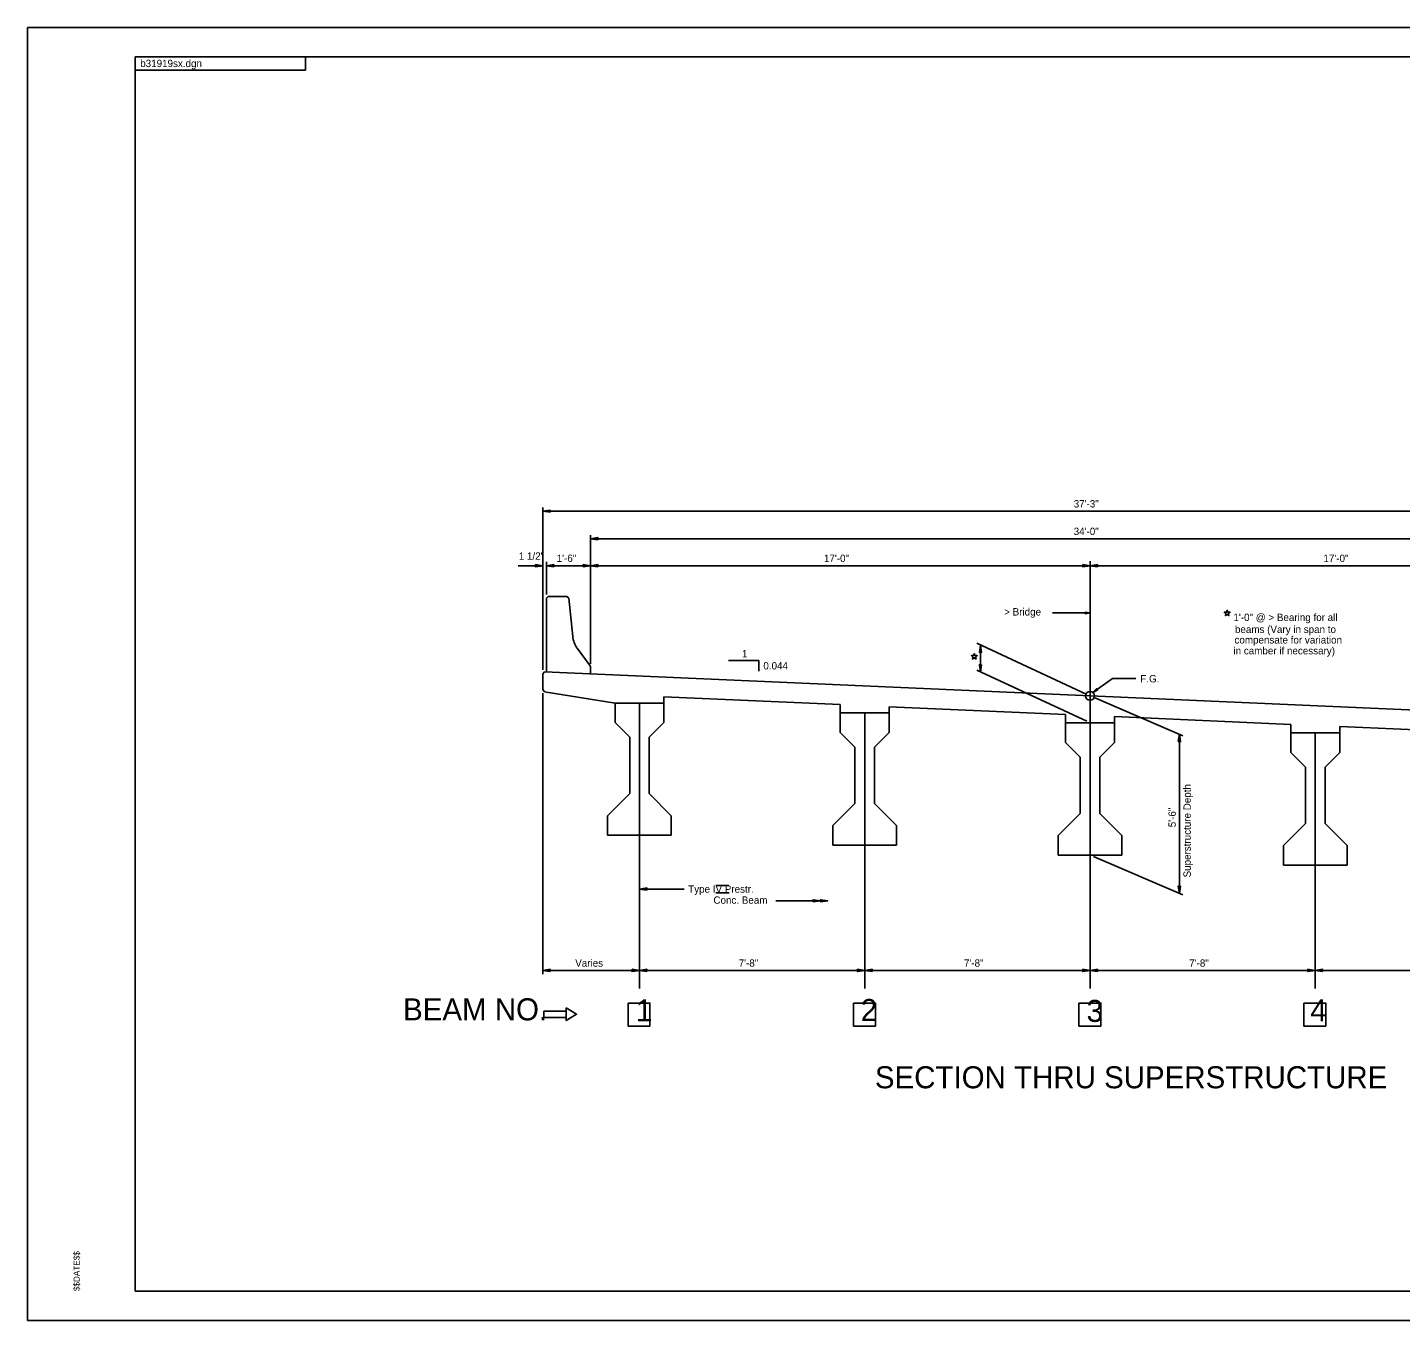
# Model space of a CAD drawing. Extents: x 9680018.4 to 9680090.7, y 4198568.1 to 4198612.1.
# Drawn here: x 9680018.44 to 9680065.17, y 4198568.13 to 4198612.13 of the extents above; entities that cross this region are included whole.
import ezdxf

# ---------------------------------------------------------------- set-up
doc = ezdxf.new("R2010")
doc.units = 0
for name, color, linetype in [('BR_AUTO DIMENSION', 7, 'Continuous'), ('BR_BORDER LINES', 7, 'Continuous'), ('BR_CENTER LINES', 7, 'Continuous'), ('BR_CONCRETE', 7, 'Continuous'), ('BR_REBAR', 7, 'Continuous'), ('BR_TEXT', 7, 'Continuous'), ('RD_SHT_IplotShp', 7, 'Continuous')]:
    doc.layers.add(name, color=color, linetype=linetype)

msp = doc.modelspace()

# ---------------------------------------------------------------- linework, layer by layer
at = {"layer": 'BR_AUTO DIMENSION'}
for p, q in [((9680035.978, 4198593.94), (9680035.978, 4198595.795)), ((9680035.978, 4198595.67), (9680073.228, 4198595.67)), ((9680037.603, 4198593.94), (9680037.603, 4198594.857)), ((9680037.603, 4198594.732), (9680071.603, 4198594.732)), ((9680035.144, 4198593.815), (9680035.978, 4198593.815)), ((9680035.978, 4198590.265), (9680035.978, 4198593.94)), ((9680036.103, 4198592.832), (9680036.103, 4198593.94)), ((9680036.103, 4198593.815), (9680054.603, 4198593.815)), ((9680037.603, 4198590.479), (9680037.603, 4198593.94)), ((9680037.999, 4198593.815), (9680037.603, 4198593.815)), ((9680054.603, 4198593.815), (9680073.103, 4198593.815)), ((9680053.327, 4198592.206), (9680054.603, 4198592.206)), ((9680054.434, 4198592.177), (9680054.434, 4198592.234)), ((9680054.434, 4198592.234), (9680054.603, 4198592.206)), ((9680054.603, 4198592.206), (9680054.434, 4198592.177)), ((9680054.468, 4198589.445), (9680050.747, 4198591.173)), ((9680050.875, 4198591.113), (9680050.875, 4198590.196)), ((9680054.49, 4198588.518), (9680050.747, 4198590.255)), ((9680035.978, 4198589.473), (9680035.978, 4198579.917)), ((9680054.74, 4198589.324), (9680057.76, 4198588.03)), ((9680057.646, 4198588.079), (9680057.646, 4198582.662)), ((9680039.603, 4198587.244), (9680039.603, 4198586.767)), ((9680047.27, 4198586.906), (9680047.27, 4198586.429)), ((9680054.936, 4198586.569), (9680054.936, 4198586.092)), ((9680062.603, 4198586.232), (9680062.603, 4198585.755)), ((9680054.718, 4198583.916), (9680057.76, 4198582.613)), ((9680040.794, 4198582.812), (9680039.27, 4198582.812)), ((9680041.867, 4198582.935), (9680042.313, 4198582.935)), ((9680041.87, 4198582.685), (9680042.316, 4198582.685)), ((9680045.677, 4198582.407), (9680043.912, 4198582.407)), ((9680035.978, 4198580.042), (9680039.27, 4198580.042)), ((9680039.27, 4198580.042), (9680046.936, 4198580.042)), ((9680039.27, 4198579.917), (9680039.27, 4198579.917)), ((9680046.936, 4198580.042), (9680054.603, 4198580.042)), ((9680046.936, 4198579.917), (9680046.936, 4198579.917)), ((9680054.603, 4198580.042), (9680062.27, 4198580.042)), ((9680054.603, 4198579.917), (9680054.603, 4198579.917)), ((9680062.27, 4198580.042), (9680069.936, 4198580.042)), ((9680062.27, 4198579.917), (9680062.27, 4198579.917))]:
    msp.add_line(p, q, dxfattribs=at)
for points in [[(9680036.228, 4198595.632), (9680035.978, 4198595.67), (9680036.228, 4198595.707)], [(9680037.853, 4198594.695), (9680037.603, 4198594.732), (9680037.853, 4198594.77)], [(9680035.728, 4198593.853), (9680035.978, 4198593.815), (9680035.728, 4198593.778)], [(9680036.353, 4198593.778), (9680036.103, 4198593.815), (9680036.353, 4198593.853)], [(9680037.353, 4198593.853), (9680037.603, 4198593.815), (9680037.353, 4198593.778)], [(9680037.853, 4198593.778), (9680037.603, 4198593.815), (9680037.853, 4198593.853)], [(9680037.853, 4198593.778), (9680037.603, 4198593.815), (9680037.853, 4198593.853)], [(9680054.353, 4198593.853), (9680054.603, 4198593.815), (9680054.353, 4198593.778)], [(9680054.853, 4198593.778), (9680054.603, 4198593.815), (9680054.853, 4198593.853)], [(9680050.838, 4198590.863), (9680050.875, 4198591.113), (9680050.913, 4198590.863)], [(9680050.913, 4198590.446), (9680050.875, 4198590.196), (9680050.838, 4198590.446)], [(9680054.864, 4198589.585), (9680054.694, 4198589.5), (9680054.832, 4198589.631)], [(9680057.608, 4198587.829), (9680057.646, 4198588.079), (9680057.683, 4198587.829)], [(9680039.52, 4198582.775), (9680039.27, 4198582.812), (9680039.52, 4198582.85)], [(9680057.683, 4198582.912), (9680057.646, 4198582.662), (9680057.608, 4198582.912)], [(9680045.177, 4198582.37), (9680045.427, 4198582.407), (9680045.177, 4198582.445)], [(9680045.427, 4198582.37), (9680045.677, 4198582.407), (9680045.427, 4198582.445)], [(9680036.228, 4198580.004), (9680035.978, 4198580.042), (9680036.228, 4198580.079)], [(9680039.02, 4198580.079), (9680039.27, 4198580.042), (9680039.02, 4198580.004)], [(9680039.52, 4198580.004), (9680039.27, 4198580.042), (9680039.52, 4198580.079)], [(9680046.686, 4198580.079), (9680046.936, 4198580.042), (9680046.686, 4198580.004)], [(9680047.186, 4198580.004), (9680046.936, 4198580.042), (9680047.186, 4198580.079)], [(9680054.353, 4198580.079), (9680054.603, 4198580.042), (9680054.353, 4198580.004)], [(9680054.853, 4198580.004), (9680054.603, 4198580.042), (9680054.853, 4198580.079)], [(9680062.02, 4198580.079), (9680062.27, 4198580.042), (9680062.02, 4198580.004)], [(9680062.52, 4198580.004), (9680062.27, 4198580.042), (9680062.52, 4198580.079)]]:
    msp.add_lwpolyline(points, close=True, dxfattribs=at)
msp.add_circle((9680054.603, 4198589.383), 0.149, dxfattribs=at)
at = {"layer": 'BR_BORDER LINES'}
for p, q in [((9680018.439, 4198612.13), (9680090.439, 4198612.13)), ((9680089.439, 4198611.127), (9680022.106, 4198611.127)), ((9680022.106, 4198569.127), (9680022.106, 4198611.127)), ((9680027.906, 4198611.127), (9680027.906, 4198610.676)), ((9680022.106, 4198610.676), (9680027.906, 4198610.676)), ((9680022.106, 4198569.127), (9680089.439, 4198569.127))]:
    msp.add_line(p, q, dxfattribs=at)
at = {"layer": 'BR_CENTER LINES'}
for p, q in [((9680054.603, 4198593.97), (9680054.603, 4198579.422)), ((9680038.436, 4198589.14), (9680040.103, 4198589.14)), ((9680039.27, 4198589.14), (9680039.27, 4198579.422)), ((9680046.103, 4198588.803), (9680047.77, 4198588.803)), ((9680046.936, 4198588.803), (9680046.936, 4198579.422)), ((9680053.77, 4198588.466), (9680055.436, 4198588.466)), ((9680061.436, 4198588.128), (9680063.103, 4198588.128)), ((9680062.27, 4198588.128), (9680062.27, 4198579.422))]:
    msp.add_line(p, q, dxfattribs=at)
at = {"layer": 'BR_CONCRETE'}
for p, q in [((9680036.166, 4198592.77), (9680036.103, 4198592.707)), ((9680036.103, 4198592.707), (9680036.103, 4198590.197)), ((9680036.166, 4198592.77), (9680036.791, 4198592.77)), ((9680036.791, 4198592.77), (9680036.86, 4198592.708)), ((9680036.996, 4198591.408), (9680036.86, 4198592.708)), ((9680037.587, 4198590.403), (9680037.15, 4198591.006)), ((9680035.978, 4198590.14), (9680036.04, 4198590.2)), ((9680035.978, 4198590.14), (9680035.978, 4198589.598)), ((9680036.04, 4198590.2), (9680073.166, 4198588.566)), ((9680037.603, 4198590.354), (9680037.603, 4198590.131)), ((9680036.04, 4198589.525), (9680035.978, 4198589.598)), ((9680036.04, 4198589.525), (9680038.436, 4198589.14)), ((9680040.103, 4198589.354), (9680046.103, 4198589.09)), ((9680047.77, 4198589.016), (9680053.77, 4198588.752)), ((9680055.436, 4198588.679), (9680061.436, 4198588.415)), ((9680063.103, 4198588.342), (9680069.103, 4198588.078))]:
    msp.add_line(p, q, dxfattribs=at)
for centre, radius, start, end in [((9680037.825, 4198591.495), 0.833, 186.009, 215.9195), ((9680037.52, 4198590.354), 0.0833, 360, 35.9195)]:
    msp.add_arc(centre, radius, start, end, dxfattribs=at)
at = {"layer": 'BR_REBAR'}
for p, q in [((9680042.303, 4198590.587), (9680043.332, 4198590.587)), ((9680043.332, 4198590.587), (9680043.332, 4198590.222)), ((9680038.436, 4198588.474), (9680038.436, 4198589.14)), ((9680038.436, 4198589.14), (9680040.103, 4198589.14)), ((9680040.103, 4198588.474), (9680040.103, 4198589.354)), ((9680046.103, 4198588.136), (9680046.103, 4198589.09)), ((9680046.103, 4198588.803), (9680047.77, 4198588.803)), ((9680047.77, 4198588.136), (9680047.77, 4198589.016)), ((9680053.77, 4198587.799), (9680053.77, 4198588.752)), ((9680055.436, 4198587.799), (9680055.436, 4198588.679)), ((9680038.436, 4198588.474), (9680038.936, 4198587.974)), ((9680040.103, 4198588.474), (9680039.603, 4198587.974)), ((9680046.103, 4198588.136), (9680046.603, 4198587.636)), ((9680047.77, 4198588.136), (9680047.27, 4198587.636)), ((9680053.77, 4198588.466), (9680055.436, 4198588.466)), ((9680061.436, 4198587.462), (9680061.436, 4198588.415)), ((9680061.436, 4198588.128), (9680063.103, 4198588.128)), ((9680063.103, 4198587.462), (9680063.103, 4198588.342)), ((9680038.936, 4198586.057), (9680038.936, 4198587.974)), ((9680039.603, 4198586.057), (9680039.603, 4198587.974)), ((9680053.77, 4198587.799), (9680054.27, 4198587.299)), ((9680055.436, 4198587.799), (9680054.936, 4198587.299)), ((9680046.603, 4198585.72), (9680046.603, 4198587.636)), ((9680047.27, 4198585.72), (9680047.27, 4198587.636)), ((9680054.27, 4198585.382), (9680054.27, 4198587.299)), ((9680054.936, 4198585.382), (9680054.936, 4198587.299)), ((9680061.436, 4198587.462), (9680061.936, 4198586.962)), ((9680063.103, 4198587.462), (9680062.603, 4198586.962)), ((9680061.936, 4198585.045), (9680061.936, 4198586.962)), ((9680062.603, 4198585.045), (9680062.603, 4198586.962)), ((9680038.936, 4198586.057), (9680038.186, 4198585.307)), ((9680039.603, 4198586.057), (9680040.353, 4198585.307)), ((9680046.603, 4198585.72), (9680045.853, 4198584.97)), ((9680047.27, 4198585.72), (9680048.02, 4198584.97)), ((9680054.27, 4198585.382), (9680053.52, 4198584.632)), ((9680054.936, 4198585.382), (9680055.686, 4198584.632)), ((9680038.186, 4198584.64), (9680038.186, 4198585.307)), ((9680040.353, 4198584.64), (9680040.353, 4198585.307)), ((9680045.853, 4198584.303), (9680045.853, 4198584.97)), ((9680048.02, 4198584.303), (9680048.02, 4198584.97)), ((9680061.936, 4198585.045), (9680061.186, 4198584.295)), ((9680062.603, 4198585.045), (9680063.353, 4198584.295)), ((9680038.186, 4198584.64), (9680040.353, 4198584.64)), ((9680053.52, 4198583.966), (9680053.52, 4198584.632)), ((9680055.686, 4198583.966), (9680055.686, 4198584.632)), ((9680045.853, 4198584.303), (9680048.02, 4198584.303)), ((9680053.52, 4198583.966), (9680055.686, 4198583.966)), ((9680061.186, 4198583.628), (9680061.186, 4198584.295)), ((9680063.353, 4198583.628), (9680063.353, 4198584.295)), ((9680061.186, 4198583.628), (9680063.353, 4198583.628))]:
    msp.add_line(p, q, dxfattribs=at)
at = {"layer": 'BR_TEXT'}
for p, q in [((9680055.37, 4198589.973), (9680054.694, 4198589.5)), ((9680056.164, 4198589.973), (9680055.37, 4198589.973))]:
    msp.add_line(p, q, dxfattribs=at)
for points in [[(9680059.235, 4198592.186), (9680059.211, 4198592.114), (9680059.272, 4198592.158), (9680059.331, 4198592.114), (9680059.309, 4198592.184), (9680059.371, 4198592.229), (9680059.295, 4198592.229), (9680059.273, 4198592.3), (9680059.249, 4198592.23), (9680059.173, 4198592.23)], [(9680050.628, 4198590.71), (9680050.603, 4198590.638), (9680050.665, 4198590.682), (9680050.723, 4198590.638), (9680050.702, 4198590.709), (9680050.764, 4198590.754), (9680050.688, 4198590.754), (9680050.666, 4198590.824), (9680050.642, 4198590.754), (9680050.566, 4198590.754)], [(9680038.881, 4198578.928), (9680039.625, 4198578.928), (9680039.625, 4198578.146), (9680038.881, 4198578.146)], [(9680046.554, 4198578.928), (9680047.298, 4198578.928), (9680047.298, 4198578.146), (9680046.554, 4198578.146)], [(9680054.227, 4198578.928), (9680054.971, 4198578.928), (9680054.971, 4198578.146), (9680054.227, 4198578.146)], [(9680061.88, 4198578.928), (9680062.625, 4198578.928), (9680062.625, 4198578.146), (9680061.88, 4198578.146)], [(9680036.017, 4198578.659), (9680036.775, 4198578.659), (9680036.775, 4198578.441), (9680036.017, 4198578.441)], [(9680036.775, 4198578.768), (9680037.128, 4198578.55), (9680036.775, 4198578.332)]]:
    msp.add_lwpolyline(points, close=True, dxfattribs=at)
at = {"layer": 'RD_SHT_IplotShp'}
for p, q in [((9680018.439, 4198612.127), (9680090.439, 4198612.127)), ((9680018.439, 4198568.127), (9680018.439, 4198612.127)), ((9680090.439, 4198568.127), (9680018.439, 4198568.127))]:
    msp.add_line(p, q, dxfattribs=at)

# ---------------------------------------------------------------- texts
at = {"layer": 'BR_AUTO DIMENSION'}
for s, p in [('37\'-3"', (9680054.048, 4198595.795)), ('34\'-0"', (9680054.048, 4198594.857)), ('1 1/2"', (9680035.162, 4198594.016)), ('1\'-6"', (9680036.452, 4198593.943)), ('17\'-0"', (9680045.548, 4198593.94)), ('17\'-0"', (9680062.548, 4198593.94)), ('> Bridge', (9680051.682, 4198592.119)), ('1', (9680042.759, 4198590.695)), ('Type IV Prestr. ', (9680040.928, 4198582.685)), ('Conc. Beam', (9680041.786, 4198582.31)), ('Varies', (9680037.083, 4198580.167)), ('7\'-8"', (9680042.646, 4198580.167)), ('7\'-8"', (9680050.313, 4198580.167)), ('7\'-8"', (9680057.98, 4198580.167))]:
    msp.add_text(s, height=0.25, dxfattribs=at).set_placement(p)
for s, rotation, p in [('Superstructure Depth', 89.9997, (9680058.033, 4198583.206)), ('5\'-6"', 90, (9680057.521, 4198584.914))]:
    msp.add_text(s, height=0.25, rotation=rotation, dxfattribs=at).set_placement(p)
at = {"layer": 'BR_TEXT'}
for s, height, p in [('b31919sx.dgn', 0.25, (9680022.278, 4198610.782)), ('1\'-0" @ > Bearing for all', 0.25, (9680059.484, 4198591.931)), ('compensate for variation', 0.25, (9680059.519, 4198591.166)), ('beams (Vary in span to', 0.25, (9680059.536, 4198591.523)), ('in camber if necessary) ', 0.25, (9680059.485, 4198590.796)), ('0.044', 0.25, (9680043.486, 4198590.283)), ('F.G. ', 0.25, (9680056.314, 4198589.843)), ('BEAM NO.', 0.75, (9680031.223, 4198578.342)), ('1', 0.75, (9680039.147, 4198578.305)), ('2', 0.75, (9680046.801, 4198578.319)), ('3', 0.75, (9680054.487, 4198578.29)), ('4', 0.75, (9680062.1, 4198578.304)), ('SECTION THRU SUPERSTRUCTURE', 0.75, (9680047.281, 4198576.03))]:
    msp.add_text(s, height=height, dxfattribs=at).set_placement(p)
msp.add_text('$$DATE$$', height=0.2083, rotation=90, dxfattribs=at).set_placement((9680020.216, 4198569.127))

doc.saveas('drawing.dxf')
